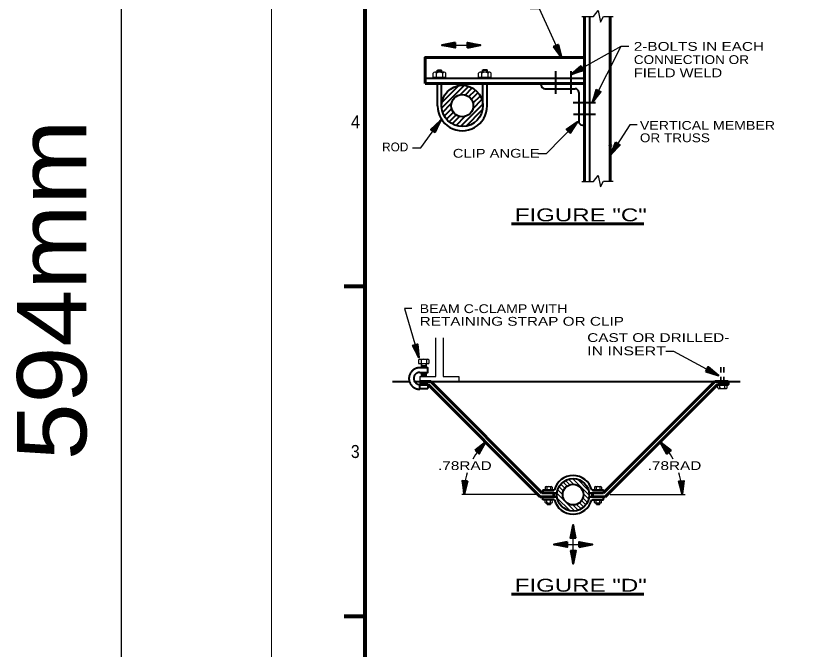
# Model space of a CAD drawing. Extents: x 55 to 190, y 198 to 264.
# Drawn here: x 55.13 to 78.22, y 217.69 to 235.95 of the extents above; entities that cross this region are included whole.
import ezdxf
from ezdxf.enums import TextEntityAlignment as Align

# ---------------------------------------------------------------- set-up
doc = ezdxf.new("R2010")
doc.units = 0
doc.header["$LTSCALE"] = 0.1
doc.header["$PDMODE"] = 32
doc.header["$PDSIZE"] = 0.05
doc.linetypes.add('SHORT_DASHED', pattern=[2.7, 1.5, -1.2])
for name, color, linetype, lineweight in [('1', 7, 'Continuous', 25), ('2', 7, 'Continuous', 40), ('3', 7, 'Continuous', 25)]:
    doc.layers.add(name, color=color, linetype=linetype, lineweight=lineweight)

msp = doc.modelspace()

# ---------------------------------------------------------------- linework, layer by layer
at = {"layer": '1', "lineweight": 80}
for p, q in [((65.1915, 228.1525), (64.5915, 228.1525)), ((65.1915, 218.6512), (64.5915, 218.6512))]:
    msp.add_line(p, q, dxfattribs=at)
at = {"layer": '1', "lineweight": 13}
msp.add_lwpolyline([(62.4915, 257.8525), (146.5927, 257.8525), (146.5927, 198.4512), (62.4915, 198.4512)], close=True, dxfattribs=at)
at = {"layer": '1', "lineweight": 80}
msp.add_lwpolyline([(65.1915, 256.6525), (145.3927, 256.6525), (145.3927, 199.6512), (65.1915, 199.6512)], close=True, dxfattribs=at)
at = {"layer": '2', "lineweight": 60}
for p, q in [((71.5133, 235.9323), (71.5133, 231.1868)), ((72.2618, 231.1852), (72.2618, 235.9323)), ((71.5133, 234.0019), (66.9238, 234.0019)), ((69.4167, 229.9564), (73.2249, 229.9564)), ((67.0836, 225.4223), (66.7994, 225.4207)), ((66.7994, 225.4207), (66.7994, 225.3358)), ((67.0836, 225.4223), (70.2832, 222.2105)), ((72.0668, 222.2118), (75.2772, 225.4223)), ((75.2783, 225.4223), (75.6556, 225.4223)), ((66.768, 225.3358), (67.0116, 225.3358)), ((67.0116, 225.3358), (70.2351, 222.1002)), ((72.1139, 222.1002), (75.3489, 225.3352)), ((70.2832, 222.2105), (70.6367, 222.2105)), ((70.6367, 222.2105), (70.6375, 222.1002)), ((71.7437, 222.2118), (71.7445, 222.1002)), ((71.7437, 222.2118), (72.0668, 222.2118)), ((70.2351, 222.1002), (70.6375, 222.1002)), ((71.7445, 222.1002), (72.1139, 222.1002)), ((69.4156, 219.2884), (73.2238, 219.2884))]:
    msp.add_line(p, q, dxfattribs=at)
at = {"layer": '2'}
for p, q in [((71.6709, 231.1852), (71.6709, 235.9323)), ((67.4053, 235.1044), (67.7877, 235.1613)), ((67.4053, 235.1044), (67.7882, 235.1399)), ((67.4053, 235.1044), (67.7877, 235.1227)), ((67.7879, 235.105), (67.4053, 235.1044)), ((67.4053, 235.1044), (67.7877, 235.0484)), ((67.4053, 235.1044), (67.7877, 235.0857)), ((68.5227, 235.1044), (68.1398, 235.069)), ((68.1401, 235.1039), (68.5227, 235.1044)), ((68.5227, 235.1044), (68.1403, 235.1605)), ((68.5227, 235.1044), (68.1403, 235.1232)), ((68.5227, 235.1044), (68.1403, 235.0862)), ((68.5227, 235.1044), (68.1403, 235.0476)), ((70.8507, 234.7515), (70.6409, 235.0761)), ((70.8507, 234.7515), (70.66, 235.0854)), ((70.8507, 234.7515), (70.6759, 235.092)), ((70.692, 235.0997), (70.8507, 234.7515)), ((70.8507, 234.7515), (70.7095, 235.1074)), ((70.8507, 234.7515), (70.7433, 235.1227)), ((67.2797, 234.3911), (67.3987, 234.3911)), ((67.2797, 234.3245), (67.2797, 234.3911)), ((67.3987, 234.3258), (67.3987, 234.3911)), ((68.5894, 234.3954), (68.7084, 234.3954)), ((68.5894, 234.3287), (68.5894, 234.3954)), ((68.7084, 234.33), (68.7084, 234.3954)), ((70.6941, 233.7053), (70.6941, 234.357)), ((71.119, 234.2612), (71.4257, 234.4967)), ((71.119, 234.2612), (71.4365, 234.4784)), ((71.119, 234.2612), (71.4442, 234.4631)), ((71.4532, 234.4477), (71.119, 234.2612)), ((71.119, 234.2612), (71.4622, 234.4308)), ((71.119, 234.2612), (71.4805, 234.3983)), ((71.1272, 234.357), (71.1272, 233.7098)), ((66.9238, 234.1596), (71.5133, 234.1596)), ((67.2797, 233.3571), (67.2797, 233.9993)), ((67.3987, 233.3571), (67.3987, 233.9993)), ((67.4117, 233.3092), (68.0393, 233.9368)), ((67.4249, 233.4757), (67.8731, 233.9239)), ((67.9382, 233.6823), (68.1647, 233.9091)), ((68.5894, 233.3571), (68.5894, 234.0035)), ((68.7084, 233.3571), (68.7084, 234.0035)), ((70.27, 233.9601), (70.27, 234.0017)), ((68.079, 233.6699), (68.2742, 233.8651)), ((68.1777, 233.6154), (68.3764, 233.8141)), ((68.2544, 233.5389), (68.4462, 233.7305)), ((70.3758, 233.8543), (71.2444, 233.8543)), ((71.3503, 233.7485), (71.3503, 232.9121)), ((71.7493, 233.4558), (71.8715, 233.8225)), ((71.7493, 233.4558), (71.8908, 233.8133)), ((71.7493, 233.4558), (71.9059, 233.8051)), ((71.9218, 233.7974), (71.7493, 233.4558)), ((71.7493, 233.4558), (71.939, 233.7884)), ((71.7493, 233.4558), (71.972, 233.7715)), ((67.426, 233.1703), (67.6784, 233.4227)), ((68.3126, 233.4439), (68.5068, 233.6379)), ((68.316, 233.2941), (68.5507, 233.5286)), ((71.191, 233.4592), (71.8334, 233.4592)), ((67.477, 233.0679), (67.6792, 233.2701)), ((67.9514, 232.7761), (68.5819, 233.4066)), ((68.1073, 232.7785), (68.5703, 233.2418)), ((67.5424, 232.9801), (67.7403, 233.178)), ((67.621, 232.9055), (67.8147, 233.0992)), ((67.7162, 232.8473), (67.9178, 233.0489)), ((67.8244, 232.8026), (68.0705, 233.0486)), ((71.8334, 233.1129), (71.2045, 233.1129)), ((67.3728, 232.9425), (67.104, 232.665)), ((67.3728, 232.9425), (67.1341, 232.643)), ((67.1495, 232.6316), (67.3728, 232.9425)), ((67.3728, 232.9425), (67.1643, 232.6216)), ((67.3728, 232.9425), (67.1778, 232.611)), ((67.3728, 232.9425), (67.1953, 232.5991)), ((71.3175, 232.8957), (71.009, 232.6629)), ((71.3175, 232.8957), (71.0354, 232.6367)), ((71.0489, 232.6229), (71.3175, 232.8957)), ((71.3175, 232.8957), (71.0619, 232.6107)), ((71.3175, 232.8957), (71.0735, 232.5983)), ((71.3175, 232.8957), (71.0891, 232.5837)), ((71.4561, 232.8063), (71.5146, 232.8063)), ((72.2631, 231.9503), (72.4234, 232.302)), ((72.2631, 231.9503), (72.4417, 232.2909)), ((72.2631, 231.9503), (72.4557, 232.2811)), ((72.4708, 232.2718), (72.2631, 231.9503)), ((72.2631, 231.9503), (72.4869, 232.261)), ((72.2631, 231.9503), (72.5181, 232.2406)), ((66.7381, 226.1099), (66.5788, 226.4623)), ((66.7381, 226.1099), (66.5994, 226.4686)), ((66.7381, 226.1099), (66.6159, 226.4726)), ((66.6331, 226.4779), (66.7381, 226.1099)), ((66.7381, 226.1099), (66.6516, 226.4827)), ((66.7381, 226.1099), (66.6873, 226.493)), ((75.3833, 225.5937), (75.0724, 225.8234)), ((75.3833, 225.5937), (75.0193, 225.7239)), ((75.3833, 225.5937), (75.029, 225.7432)), ((75.3833, 225.5937), (75.0375, 225.7578)), ((75.0457, 225.7736), (75.3833, 225.5937)), ((75.3833, 225.5937), (75.055, 225.7906)), ((65.9819, 225.4223), (66.4685, 225.4223)), ((66.6161, 225.4223), (76.0009, 225.4223)), ((66.768, 225.1932), (66.768, 225.3334)), ((66.768, 225.2191), (67.0013, 225.2191)), ((67.0013, 225.3334), (67.0013, 225.2191)), ((68.6735, 223.6781), (68.3785, 223.4281)), ((68.6735, 223.6781), (68.3944, 223.4136)), ((68.6735, 223.6781), (68.4073, 223.403)), ((68.4205, 223.3911), (68.6735, 223.6781)), ((68.6735, 223.6781), (68.4354, 223.3784)), ((68.6735, 223.6781), (68.4631, 223.354)), ((73.954, 223.3911), (73.7011, 223.6781)), ((73.7011, 223.6781), (73.9802, 223.4136)), ((73.7011, 223.6781), (73.9114, 223.354)), ((73.7011, 223.6781), (73.9392, 223.3784)), ((73.7011, 223.6781), (73.9673, 223.403)), ((73.7011, 223.6781), (73.9961, 223.4281)), ((68.044, 222.175), (68.0149, 222.5603)), ((68.044, 222.175), (68.0522, 222.5579)), ((68.0713, 222.5566), (68.044, 222.175)), ((68.044, 222.175), (68.0893, 222.5553)), ((68.044, 222.175), (68.1062, 222.5545)), ((68.044, 222.175), (68.1274, 222.5526)), ((74.3305, 222.175), (74.2472, 222.5526)), ((74.3305, 222.175), (74.2684, 222.5545)), ((74.3305, 222.175), (74.2853, 222.5553)), ((74.3033, 222.5566), (74.3305, 222.175)), ((74.3305, 222.175), (74.3223, 222.5579)), ((74.3305, 222.175), (74.3596, 222.5603)), ((70.315, 222.2997), (70.315, 222.2105)), ((70.3171, 222.2991), (70.6494, 222.2991)), ((70.6367, 222.2105), (70.7232, 222.2105)), ((71.6527, 222.2118), (71.7437, 222.2118)), ((71.726, 222.2997), (72.0604, 222.2997)), ((72.0604, 222.2997), (72.0604, 222.2126)), ((70.3152, 222.011), (70.3152, 222.1002)), ((70.6497, 222.011), (70.3152, 222.011)), ((70.6375, 222.1002), (70.7232, 222.1002)), ((71.653, 222.1002), (71.7445, 222.1002)), ((71.726, 222.011), (72.0604, 222.011)), ((72.0604, 222.011), (72.0604, 222.1002)), ((71.1899, 221.2868), (71.1338, 220.9045)), ((71.1899, 221.2868), (71.1712, 220.9045)), ((71.1905, 220.9043), (71.1899, 221.2868)), ((71.1899, 221.2868), (71.2254, 220.904)), ((71.1899, 221.2868), (71.2082, 220.9045)), ((71.1899, 221.2868), (71.2468, 220.9045)), ((70.6314, 220.728), (71.0137, 220.7849)), ((70.6314, 220.728), (71.0143, 220.7635)), ((70.6314, 220.728), (71.0137, 220.7463)), ((71.014, 220.7286), (70.6314, 220.728)), ((70.6314, 220.728), (71.0137, 220.6719)), ((70.6314, 220.728), (71.0137, 220.7092)), ((71.7487, 220.728), (71.3659, 220.6926)), ((71.3661, 220.7275), (71.7487, 220.728)), ((71.7487, 220.728), (71.3664, 220.7841)), ((71.7487, 220.728), (71.3664, 220.7468)), ((71.7487, 220.728), (71.3664, 220.7098)), ((71.7487, 220.728), (71.3664, 220.6712)), ((71.1899, 220.1695), (71.1331, 220.5518)), ((71.1899, 220.1695), (71.1545, 220.5523)), ((71.1899, 220.1695), (71.1717, 220.5518)), ((71.1894, 220.5521), (71.1899, 220.1695)), ((71.1899, 220.1695), (71.246, 220.5518)), ((71.1899, 220.1695), (71.2087, 220.5518))]:
    msp.add_line(p, q, dxfattribs=at)
at = {"layer": '2', "lineweight": 25}
for p, q in [((67.4053, 235.1044), (68.5227, 235.1044)), ((72.5663, 235.0666), (71.7493, 233.4558)), ((67.1561, 234.1718), (67.1561, 234.2975)), ((67.5196, 234.1718), (67.1561, 234.1718)), ((67.4739, 234.3258), (67.2016, 234.326)), ((67.2466, 234.1718), (67.2466, 234.2985)), ((67.4294, 234.1718), (67.4294, 234.2985)), ((67.5196, 234.1718), (67.5196, 234.2985)), ((68.4658, 234.176), (68.4658, 234.3017)), ((68.8293, 234.176), (68.4658, 234.176)), ((68.7836, 234.33), (68.5113, 234.3303)), ((68.5563, 234.176), (68.5563, 234.3028)), ((68.7391, 234.176), (68.7391, 234.3028)), ((68.8293, 234.176), (68.8293, 234.3028)), ((66.7357, 226.0393), (66.7349, 225.9348)), ((66.7725, 226.0618), (66.9968, 226.0618)), ((66.8092, 226.039), (66.8092, 225.9348)), ((66.96, 226.0393), (66.96, 225.934)), ((67.0344, 226.0393), (67.0347, 225.9348)), ((66.7349, 225.9348), (67.0347, 225.9348)), ((66.768, 225.5657), (66.768, 225.4207)), ((75.3555, 225.3278), (75.6278, 225.3278)), ((75.3561, 225.2323), (75.3555, 225.3278)), ((75.3899, 225.2119), (75.5939, 225.2138)), ((75.423, 225.2331), (75.423, 225.3273)), ((75.5603, 225.2331), (75.5603, 225.3281)), ((75.6283, 225.2334), (75.6278, 225.3278)), ((70.3827, 222.3764), (70.3824, 222.3049)), ((70.4081, 222.3917), (70.5613, 222.3917)), ((70.433, 222.3761), (70.433, 222.3049)), ((70.5359, 222.3764), (70.5359, 222.3047)), ((70.5867, 222.3764), (70.587, 222.3049)), ((71.804, 222.378), (71.8038, 222.3065)), ((71.8294, 222.3933), (71.9826, 222.3933)), ((71.8543, 222.378), (71.8543, 222.3065)), ((71.9572, 222.378), (71.9572, 222.3065)), ((72.008, 222.378), (72.0083, 222.3065)), ((70.1149, 222.1597), (67.9766, 222.1597)), ((70.3824, 222.3049), (70.587, 222.3049)), ((71.8038, 222.3065), (72.0083, 222.3065)), ((72.253, 222.1597), (74.4231, 222.1597)), ((70.3845, 222.0036), (70.5891, 222.0062)), ((70.3859, 221.9322), (70.3845, 222.0036)), ((70.4115, 221.9173), (70.5647, 221.9195)), ((70.4361, 221.933), (70.4353, 222.0039)), ((70.5391, 221.9343), (70.5383, 222.006)), ((70.5904, 221.9351), (70.5891, 222.0062)), ((71.8059, 222.0052), (72.0104, 222.0081)), ((71.8072, 221.9337), (71.8059, 222.0052)), ((71.8329, 221.9189), (71.9863, 221.921)), ((71.8577, 221.9348), (71.8567, 222.006)), ((71.9604, 221.9359), (71.9596, 222.0076)), ((72.0115, 221.9369), (72.0104, 222.0081)), ((71.1899, 220.1695), (71.1899, 221.2868)), ((70.6314, 220.728), (71.7487, 220.728))]:
    msp.add_line(p, q, dxfattribs=at)
at = {"layer": '2', "lineweight": 35}
for p, q in [((66.9495, 225.8721), (66.8177, 225.8721)), ((66.8177, 225.8453), (66.9495, 225.8453)), ((66.8182, 225.8144), (66.8182, 225.9337)), ((66.9487, 225.8144), (66.9487, 225.9337)), ((66.9495, 225.6583), (66.8177, 225.6583)), ((66.9479, 225.5937), (66.8177, 225.5937)), ((66.8182, 225.5646), (66.8182, 225.6818)), ((66.8193, 225.6223), (66.9495, 225.6223)), ((66.9487, 225.6818), (66.9487, 225.5646))]:
    msp.add_line(p, q, dxfattribs=at)
at = {"layer": '2', "linetype": 'SHORT_DASHED', "lineweight": 35}
for p, q in [((75.4505, 225.8274), (75.4505, 225.4239)), ((75.537, 225.8274), (75.537, 225.4239))]:
    msp.add_line(p, q, dxfattribs=at)
at = {"layer": '2', "lineweight": 13}
for p, q in [((71.2092, 222.4568), (71.0606, 222.6058)), ((71.659, 222.1319), (71.1667, 222.6243)), ((71.6463, 222.269), (71.3032, 222.6116)), ((70.9074, 222.2624), (70.7841, 222.3857)), ((70.9518, 222.3423), (70.8349, 222.4592)), ((71.015, 222.4034), (70.8976, 222.5206)), ((71.0979, 222.4441), (70.9725, 222.5698)), ((71.2304, 221.6914), (70.7264, 222.1954)), ((70.8899, 222.1557), (70.7468, 222.2991)), ((71.6405, 222.0253), (71.4842, 222.1822)), ((71.0981, 221.6991), (70.7341, 222.0629)), ((71.4207, 221.7491), (71.2892, 221.8806)), ((71.4939, 221.8001), (71.3693, 221.9248)), ((71.5553, 221.8626), (71.4302, 221.988)), ((71.6045, 221.9377), (71.4712, 222.0711)), ((71.3341, 221.7118), (71.1831, 221.8628))]:
    msp.add_line(p, q, dxfattribs=at)
at = {"layer": '2', "lineweight": 25}
for points in [[(69.952, 236.1636), (70.2089, 236.1636), (70.8507, 234.7515)], [(71.4389, 235.9305), (71.7813, 235.9305), (71.9128, 236.1025), (71.9765, 235.768), (72.0657, 235.9323), (72.3403, 235.9323)], [(72.7997, 235.0666), (72.5663, 235.0666), (71.119, 234.2612)], [(66.5558, 232.1488), (66.801, 232.1488), (67.3728, 232.9425)], [(70.1739, 231.9855), (70.4189, 231.9855), (71.3175, 232.8957)], [(73.0333, 232.8139), (72.8232, 232.8139), (72.2631, 231.9503)], [(71.4389, 231.1849), (71.7813, 231.1849), (71.9128, 231.3569), (71.9765, 231.0225), (72.0657, 231.1868), (72.3403, 231.1868)], [(66.5398, 227.5228), (66.3278, 227.5228), (66.7381, 226.1099)], [(66.768, 225.5657), (67.2328, 225.5657), (67.2328, 226.6788)], [(67.4461, 226.6788), (67.4461, 225.5657), (67.894, 225.5657), (67.894, 225.4207)], [(73.8583, 226.2906), (74.0802, 226.2906), (75.3833, 225.5937)]]:
    msp.add_lwpolyline(points, dxfattribs=at)
at = {"layer": '2'}
for points in [[(67.7877, 235.1806), (67.7874, 235.0277), (67.4053, 235.1044)], [(67.7877, 235.1806), (67.4053, 235.1044), (67.7879, 235.0669)], [(68.1403, 235.0282), (68.5227, 235.1044), (68.1401, 235.142)], [(68.1403, 235.0282), (68.1406, 235.1812), (68.5227, 235.1044)], [(70.6232, 235.0679), (70.7626, 235.1312), (70.8507, 234.7515)], [(70.6232, 235.0679), (70.8507, 234.7515), (70.7267, 235.1153)], [(71.4162, 234.5139), (71.4902, 234.38), (71.119, 234.2612)], [(71.4162, 234.5139), (71.119, 234.2612), (71.4717, 234.4144)], [(71.8543, 233.8313), (71.9906, 233.7619), (71.7493, 233.4558)], [(71.8543, 233.8313), (71.7493, 233.4558), (71.9559, 233.7802)], [(67.2111, 232.5877), (67.087, 232.6774), (67.3728, 232.9425)], [(67.2111, 232.5877), (67.3728, 232.9425), (67.1185, 232.6539)], [(71.1032, 232.57), (70.9944, 232.6777), (71.3175, 232.8957)], [(71.1032, 232.57), (71.3175, 232.8957), (71.0219, 232.6499)], [(72.4073, 232.3126), (72.5353, 232.2292), (72.2631, 231.9503)], [(72.4073, 232.3126), (72.2631, 231.9503), (72.5028, 232.2509)], [(66.5603, 226.4567), (66.7074, 226.4985), (66.7381, 226.1099)], [(66.5603, 226.4567), (66.7381, 226.1099), (66.6696, 226.4882)], [(66.768, 225.8149), (66.7484, 225.8144), (66.7291, 225.8125), (66.7097, 225.8094), (66.6907, 225.8051), (66.6719, 225.7998), (66.6537, 225.7932), (66.6357, 225.7853), (66.6185, 225.7766), (66.6015, 225.7668), (66.5854, 225.7557), (66.5701, 225.7437), (66.5555, 225.7308), (66.5417, 225.717), (66.5288, 225.7025), (66.5169, 225.6871), (66.5058, 225.671), (66.496, 225.6541), (66.4872, 225.6369), (66.4793, 225.6189), (66.4727, 225.6006), (66.4674, 225.5818), (66.4632, 225.5628), (66.46, 225.5435), (66.4581, 225.5241), (66.4576, 225.5046), (66.4581, 225.4852), (66.46, 225.4657), (66.4632, 225.4466), (66.4674, 225.4276), (66.4727, 225.4088), (66.4793, 225.3905), (66.4872, 225.3725), (66.496, 225.3551), (66.5058, 225.3384), (66.5169, 225.3223), (66.5288, 225.3069), (66.5417, 225.2924), (66.5555, 225.2783), (66.5701, 225.2656), (66.5854, 225.2537), (66.6015, 225.2426), (66.6185, 225.2328), (66.6357, 225.2238), (66.6537, 225.2162), (66.6719, 225.2096), (66.6907, 225.204), (66.7097, 225.1998), (66.7291, 225.1969), (66.7484, 225.195), (66.768, 225.1945)], [(66.768, 225.6808), (67.0005, 225.6808), (67.0005, 225.8144), (66.768, 225.8144)], [(75.0103, 225.7067), (75.0825, 225.8416), (75.3833, 225.5937)], [(75.0103, 225.7067), (75.3833, 225.5937), (75.0637, 225.8072)], [(66.768, 225.6808), (66.7568, 225.6805), (66.746, 225.6795), (66.7354, 225.6779), (66.7246, 225.6755), (66.7142, 225.6723), (66.7039, 225.6686), (66.6939, 225.6644), (66.6841, 225.6593), (66.6748, 225.6538), (66.6658, 225.6477), (66.6571, 225.6411), (66.6489, 225.6337), (66.6412, 225.626), (66.6341, 225.6178), (66.6272, 225.6093), (66.6211, 225.6003), (66.6156, 225.5908), (66.6105, 225.581), (66.6063, 225.571), (66.6026, 225.5609), (66.5997, 225.5503), (66.5973, 225.5397), (66.5955, 225.5289), (66.5944, 225.5181), (66.5941, 225.5072), (66.5944, 225.4964), (66.5955, 225.4852), (66.5973, 225.4747), (66.5997, 225.4638), (66.6026, 225.4535), (66.6063, 225.4432), (66.6105, 225.4331), (66.6156, 225.4233), (66.6211, 225.4141), (66.6272, 225.4051), (66.6341, 225.3964), (66.6412, 225.3881), (66.6489, 225.3805), (66.6571, 225.3733), (66.6658, 225.3665), (66.6748, 225.3604), (66.6841, 225.3548), (66.6939, 225.35), (66.7039, 225.3456), (66.7142, 225.3418), (66.7246, 225.3389), (66.7354, 225.3365), (66.746, 225.3347), (66.7568, 225.3336), (66.768, 225.3334)], [(68.3639, 223.4408), (68.4793, 223.3403), (68.6735, 223.6781)], [(68.3639, 223.4408), (68.6735, 223.6781), (68.4491, 223.3657)], [(74.0107, 223.4408), (73.8953, 223.3403), (73.7011, 223.6781)], [(74.0107, 223.4408), (73.7011, 223.6781), (73.9255, 223.3657)], [(68.147, 222.551), (67.994, 222.5619), (68.044, 222.175)], [(68.147, 222.551), (68.044, 222.175), (68.0332, 222.5595)], [(74.2276, 222.551), (74.3805, 222.5619), (74.3305, 222.175)], [(74.2276, 222.551), (74.3305, 222.175), (74.3414, 222.5595)], [(71.2661, 220.9045), (71.1132, 220.9048), (71.1899, 221.2868)], [(71.2661, 220.9045), (71.1899, 221.2868), (71.1524, 220.9043)], [(71.0137, 220.8042), (71.0135, 220.6513), (70.6314, 220.728)], [(71.0137, 220.8042), (70.6314, 220.728), (71.014, 220.6905)], [(71.3664, 220.6518), (71.7487, 220.728), (71.3661, 220.7656)], [(71.3664, 220.6518), (71.3667, 220.8048), (71.7487, 220.728)], [(71.1137, 220.5518), (71.1899, 220.1695), (71.2275, 220.5521)], [(71.1137, 220.5518), (71.2667, 220.5516), (71.1899, 220.1695)]]:
    msp.add_lwpolyline(points, dxfattribs=at)
at = {"layer": '2', "lineweight": 60}
for points in [[(71.5133, 234.7504), (66.9238, 234.7504), (66.9238, 234.0019)], [(75.3489, 225.3352), (75.6556, 225.3352), (75.6556, 225.4223)]]:
    msp.add_lwpolyline(points, dxfattribs=at)
at = {"layer": '2', "lineweight": 35}
for points in [[(70.4425, 221.9184), (70.4428, 221.8785), (70.533, 221.8785), (70.533, 221.9184)], [(71.8636, 221.9203), (71.8638, 221.88), (71.9541, 221.88), (71.9541, 221.9203)]]:
    msp.add_lwpolyline(points, dxfattribs=at)
at = {"layer": '2'}
for centre, radius in [((67.9928, 233.3629), 0.3195), ((71.1886, 222.1547), 0.4675), ((71.1873, 222.1603), 0.2976)]:
    msp.add_circle(centre, radius, dxfattribs=at)
at = {"layer": '2', "lineweight": 25}
for centre, radius, start, end in [((67.2016, 234.2747), 0.0509, 28.1609, 153.21731), ((67.338, 234.1579), 0.168, 57.05703, 122.99384), ((67.4744, 234.2751), 0.0509, 27.96581, 152.1123), ((68.5113, 234.279), 0.0509, 28.1609, 153.21731), ((68.6477, 234.1621), 0.168, 57.05703, 122.99384), ((68.7841, 234.2794), 0.0509, 27.96581, 152.1123), ((66.7721, 226.0195), 0.0419, 27.91313, 152.05962), ((66.8844, 225.923), 0.1384, 57.03159, 122.96841), ((66.9971, 226.019), 0.0424, 28.34206, 151.66132), ((75.3895, 225.2506), 0.0381, 208.16061, 332.3071), ((75.4913, 225.3387), 0.1258, 237.25182, 303.18864), ((75.594, 225.2518), 0.0386, 208.55891, 331.87817), ((70.1536, 222.1752), 2.1095, 134.56125, 151.61924), ((72.221, 222.1752), 2.1095, 28.38076, 45.43875), ((70.1536, 222.1752), 2.1095, 162.97004, 180), ((72.221, 222.1752), 2.1095, 0, 17.02996), ((70.4078, 222.3629), 0.0286, 27.91313, 152.05962), ((70.4845, 222.297), 0.0945, 57.03159, 122.96841), ((70.5615, 222.3626), 0.029, 28.34206, 151.66132), ((71.8291, 222.3646), 0.0286, 27.91313, 152.05962), ((71.9058, 222.2987), 0.0945, 57.03159, 122.96841), ((71.9828, 222.3642), 0.029, 28.34206, 151.66132), ((70.4108, 221.9459), 0.0286, 208.78561, 332.9321), ((70.4866, 222.0129), 0.0945, 237.87682, 303.81364), ((70.5645, 221.9485), 0.029, 209.18391, 332.50317), ((71.8322, 221.9476), 0.0286, 208.78561, 332.9321), ((71.9079, 222.0146), 0.0945, 237.87682, 303.81364), ((71.9858, 221.9502), 0.029, 209.18391, 332.50317)]:
    msp.add_arc(centre, radius, start, end, dxfattribs=at)
at = {"layer": '2'}
for centre, radius, start, end in [((70.3758, 233.9601), 0.1058, 180, 270), ((71.2444, 233.7484), 0.1058, 0, 90), ((67.9941, 233.3571), 0.7144, 179.9664, 0), ((71.4561, 232.9121), 0.1058, 180, 270), ((71.1878, 222.1553), 0.5572, 15.01092, 164.9726), ((71.1877, 222.1553), 0.5572, 194.97776, 344.98899)]:
    msp.add_arc(centre, radius, start, end, dxfattribs=at)
msp.add_ellipse((67.9941, 233.3571), major_axis=(0.1032, 0.5863), ratio=0.999997, dxfattribs=at)
msp.add_point((72.2623, 232.2176), dxfattribs=at)
at = {"layer": '3'}
msp.add_line((58.1602, 257.8525), (58.1602, 198.4512), dxfattribs=at)

# ---------------------------------------------------------------- texts
at = {"layer": '1'}
for s, width, p in [('4', 0.95, (64.9181, 232.715)), ('3', 0.9, (64.9092, 223.215))]:
    msp.add_text(s, height=0.375, dxfattribs=dict(at, width=width)).set_placement(p, align=Align.CENTER)
at = {"layer": '2'}
for s, width, p in [('2-BOLTS IN EACH', 1.3, (72.9386, 234.9449)), ('CONNECTION OR', 1.15, (72.9386, 234.5639)), ('FIELD WELD', 1.25, (72.9386, 234.1829)), ('VERTICAL MEMBER', 1.2, (73.1135, 232.67)), ('OR TRUSS', 1.15, (73.1137, 232.3126)), ('BEAM C-CLAMP WITH', 1.2, (66.7661, 227.39)), ('RETAINING STRAP OR CLIP', 1.3, (66.7661, 227.0257)), ('CAST OR DRILLED-', 1.3, (71.5955, 226.5563)), ('IN INSERT', 1.35, (71.5955, 226.1753))]:
    msp.add_text(s, height=0.254, dxfattribs=dict(at, width=width)).set_placement(p)
msp.add_text('ROD', height=0.254, dxfattribs=at).set_placement((66.4388, 232.0482), align=Align.RIGHT)
at = {"layer": '2', "width": 1.25}
msp.add_text('CLIP ANGLE', height=0.254, dxfattribs=at).set_placement((70.2229, 231.8654), align=Align.RIGHT)
at = {"layer": '2'}
for s, height, width, p in [('FIGURE "C"', 0.3704, 1.4, (71.4103, 230.0334)), ('.78RAD', 0.254, 1.3, (68.0686, 222.8688)), ('.78RAD', 0.254, 1.3, (74.1119, 222.8688)), ('FIGURE "D"', 0.3704, 1.4, (71.4093, 219.3654))]:
    msp.add_text(s, height=height, dxfattribs=dict(at, width=width)).set_placement(p, align=Align.CENTER)
at = {"layer": '3', "width": 1.1}
msp.add_text('594mm', height=2, rotation=90, dxfattribs=at).set_placement((57.1602, 223.1525))

doc.saveas('drawing.dxf')
